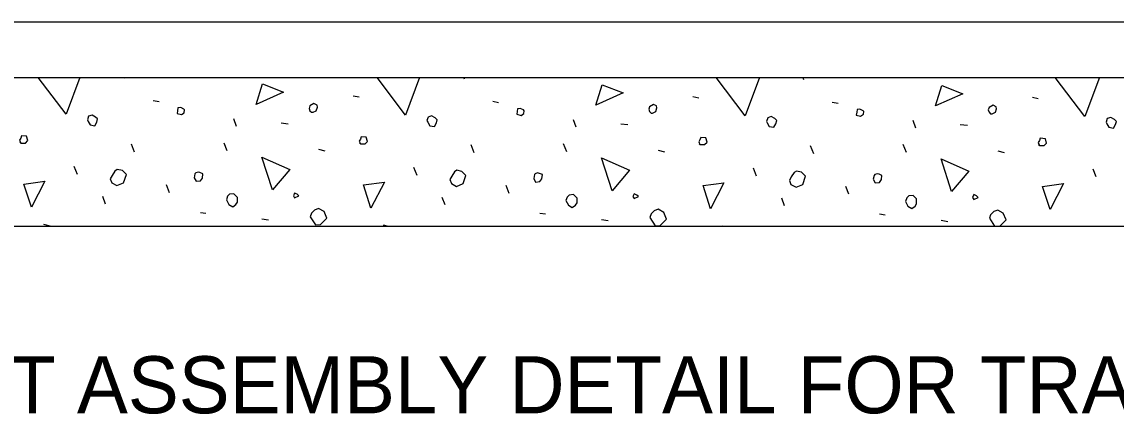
# Model space of a CAD drawing. Extents: x 110698 to 110915, y 110390 to 110472.
# Drawn here: x 110880.112 to 110885.022, y 110456.769 to 110458.529 of the extents above; entities that cross this region are included whole.
import ezdxf

# ---------------------------------------------------------------- set-up
doc = ezdxf.new("R2010")
doc.units = 0
for name, color, linetype in [('Border', 7, 'Continuous'), ('SheetBorder_dp', 7, 'Continuous'), ('SheetLines_dp', 7, 'Continuous'), ('SupstrConc_h', 7, 'Continuous')]:
    doc.layers.add(name, color=color, linetype=linetype)

msp = doc.modelspace()

# ---------------------------------------------------------------- linework, layer by layer
at = {"layer": 'SheetBorder_dp'}
for p, q in [((110880.5736, 110458.2752), (110880.5723, 110458.2787)), ((110882.0974, 110458.2716), (110882.0948, 110458.2787)), ((110883.6212, 110458.2681), (110883.6173, 110458.2787)), ((110881.5989, 110458.1974), (110881.6254, 110458.1921)), ((110883.1227, 110458.1939), (110883.1492, 110458.1885)), ((110884.6465, 110458.1903), (110884.673, 110458.185)), ((110880.7009, 110458.1762), (110880.7274, 110458.1709)), ((110882.2247, 110458.1726), (110882.2512, 110458.1673)), ((110883.7485, 110458.1691), (110883.775, 110458.1638)), ((110881.0756, 110458.0595), (110881.0633, 110458.0931)), ((110882.5995, 110458.056), (110882.5871, 110458.0896)), ((110884.1233, 110458.0524), (110884.1109, 110458.086)), ((110881.2754, 110458.0754), (110881.3072, 110458.0719)), ((110882.7992, 110458.0719), (110882.831, 110458.0683)), ((110884.323, 110458.0683), (110884.3548, 110458.0648)), ((110881.0332, 110457.9499), (110881.0191, 110457.9853)), ((110882.557, 110457.9464), (110882.5429, 110457.9817)), ((110880.6178, 110457.9446), (110880.6036, 110457.98)), ((110881.4433, 110457.957), (110881.4716, 110457.9499)), ((110882.1416, 110457.9411), (110882.1275, 110457.9764)), ((110882.9671, 110457.9534), (110882.9954, 110457.9464)), ((110883.6654, 110457.9375), (110883.6513, 110457.9729)), ((110884.0808, 110457.9428), (110884.0667, 110457.9782)), ((110884.491, 110457.9499), (110884.5192, 110457.9428)), ((110880.3615, 110457.8438), (110880.3473, 110457.8792)), ((110881.8853, 110457.8403), (110881.8711, 110457.8757)), ((110883.4091, 110457.8368), (110883.3949, 110457.8721)), ((110884.9329, 110457.8332), (110884.9188, 110457.8686)), ((110880.7751, 110457.7625), (110880.761, 110457.7979)), ((110882.2989, 110457.759), (110882.2848, 110457.7943)), ((110883.8227, 110457.7554), (110883.8086, 110457.7908)), ((110880.487, 110457.7113), (110880.4746, 110457.7448)), ((110882.0108, 110457.7077), (110881.9984, 110457.7413)), ((110883.5346, 110457.7042), (110883.5222, 110457.7378)), ((110880.913, 110457.6741), (110880.9378, 110457.6706)), ((110881.1888, 110457.6458), (110881.2188, 110457.6405)), ((110882.4368, 110457.6706), (110882.4616, 110457.6671)), ((110882.7126, 110457.6423), (110882.7426, 110457.637)), ((110883.9606, 110457.6671), (110883.9854, 110457.6635)), ((110884.2364, 110457.6388), (110884.2665, 110457.6335)), ((110880.2094, 110457.6211), (110880.2377, 110457.614)), ((110881.7332, 110457.6176), (110881.7553, 110457.612)), ((110883.2571, 110457.614), (110883.265, 110457.612))]:
    msp.add_line(p, q, dxfattribs=at)
for points in [[(110880.3102, 110458.1143), (110880.1852, 110458.2787)], [(110880.3716, 110458.2787), (110880.3102, 110458.1143)], [(110881.834, 110458.1108), (110881.7064, 110458.2787)], [(110881.8968, 110458.2787), (110881.834, 110458.1108)], [(110883.3578, 110458.1072), (110883.2275, 110458.2787)], [(110883.4219, 110458.2787), (110883.3578, 110458.1072)], [(110884.8816, 110458.1037), (110884.7486, 110458.2787)], [(110884.947, 110458.2787), (110884.8816, 110458.1037)], [(110881.164, 110458.1585), (110881.1923, 110458.2504), (110881.286, 110458.2133), (110881.164, 110458.1585)], [(110882.6878, 110458.155), (110882.7161, 110458.2469), (110882.8098, 110458.2098), (110882.6878, 110458.155)], [(110884.2117, 110458.1514), (110884.2399, 110458.2433), (110884.3336, 110458.2062), (110884.2117, 110458.1514)], [(110880.8087, 110458.1178), (110880.8281, 110458.1125), (110880.8405, 110458.1214), (110880.8423, 110458.1337), (110880.8388, 110458.1373), (110880.8246, 110458.1444), (110880.8122, 110458.1426), (110880.8105, 110458.1302), (110880.8087, 110458.1178)], [(110881.4115, 110458.1231), (110881.4186, 110458.1231), (110881.4327, 110458.1302), (110881.438, 110458.1461), (110881.4363, 110458.155), (110881.4221, 110458.162), (110881.4044, 110458.1514), (110881.4009, 110458.1408), (110881.4044, 110458.1302), (110881.4115, 110458.1231)], [(110882.3325, 110458.1143), (110882.352, 110458.109), (110882.3643, 110458.1178), (110882.3661, 110458.1302), (110882.3626, 110458.1337), (110882.3484, 110458.1408), (110882.3361, 110458.1391), (110882.3343, 110458.1267), (110882.3325, 110458.1143)], [(110882.9353, 110458.1196), (110882.9424, 110458.1196), (110882.9565, 110458.1267), (110882.9618, 110458.1426), (110882.9601, 110458.1514), (110882.9459, 110458.1585), (110882.9283, 110458.1479), (110882.9247, 110458.1373), (110882.9283, 110458.1267), (110882.9353, 110458.1196)], [(110883.8563, 110458.1108), (110883.8758, 110458.1055), (110883.8882, 110458.1143), (110883.8899, 110458.1267), (110883.8864, 110458.1302), (110883.8722, 110458.1373), (110883.8599, 110458.1355), (110883.8581, 110458.1231), (110883.8563, 110458.1108)], [(110884.4591, 110458.1161), (110884.4662, 110458.1161), (110884.4804, 110458.1231), (110884.4857, 110458.1391), (110884.4839, 110458.1479), (110884.4697, 110458.155), (110884.4521, 110458.1444), (110884.4485, 110458.1337), (110884.4521, 110458.1231), (110884.4591, 110458.1161)], [(110880.4092, 110458.0825), (110880.418, 110458.0666), (110880.4392, 110458.063), (110880.4481, 110458.0789), (110880.4516, 110458.0931), (110880.4428, 110458.1019), (110880.4269, 110458.1108), (110880.411, 110458.1055), (110880.4057, 110458.0896), (110880.4092, 110458.0825)], [(110881.933, 110458.0789), (110881.9418, 110458.063), (110881.9631, 110458.0595), (110881.9719, 110458.0754), (110881.9754, 110458.0896), (110881.9666, 110458.0984), (110881.9507, 110458.1072), (110881.9348, 110458.1019), (110881.9295, 110458.086), (110881.933, 110458.0789)], [(110883.4568, 110458.0754), (110883.4657, 110458.0595), (110883.4869, 110458.056), (110883.4957, 110458.0719), (110883.4992, 110458.086), (110883.4904, 110458.0949), (110883.4745, 110458.1037), (110883.4586, 110458.0984), (110883.4533, 110458.0825), (110883.4568, 110458.0754)], [(110884.9806, 110458.0719), (110884.9895, 110458.056), (110885.0107, 110458.0524), (110885.0195, 110458.0683), (110885.0231, 110458.0825), (110885.0142, 110458.0913), (110884.9983, 110458.1002), (110884.9824, 110458.0949), (110884.9771, 110458.0789), (110884.9806, 110458.0719)], [(110880.1069, 110457.9853), (110880.1281, 110457.9853), (110880.1387, 110457.9959), (110880.1334, 110458.0153), (110880.1104, 110458.0171), (110880.1069, 110458.0065), (110880.1016, 110457.9976), (110880.1069, 110457.9853), (110880.1034, 110457.9888)], [(110881.6307, 110457.9817), (110881.6519, 110457.9817), (110881.6625, 110457.9923), (110881.6572, 110458.0118), (110881.6343, 110458.0135), (110881.6307, 110458.0029), (110881.6254, 110457.9941), (110881.6307, 110457.9817), (110881.6272, 110457.9853)], [(110883.1545, 110457.9782), (110883.1757, 110457.9782), (110883.1864, 110457.9888), (110883.181, 110458.0082), (110883.1581, 110458.01), (110883.1545, 110457.9994), (110883.1492, 110457.9906), (110883.1545, 110457.9782), (110883.151, 110457.9817)], [(110884.6783, 110457.9746), (110884.6996, 110457.9746), (110884.7102, 110457.9853), (110884.7049, 110458.0047), (110884.6819, 110458.0065), (110884.6783, 110457.9959), (110884.673, 110457.987), (110884.6783, 110457.9746), (110884.6748, 110457.9782)], [(110881.2365, 110457.7749), (110881.1888, 110457.9216), (110881.3143, 110457.8668), (110881.2365, 110457.7749)], [(110882.7603, 110457.7714), (110882.7126, 110457.9181), (110882.8381, 110457.8633), (110882.7603, 110457.7714)], [(110884.2841, 110457.7678), (110884.2364, 110457.9145), (110884.3619, 110457.8597), (110884.2841, 110457.7678)], [(110880.5153, 110457.8067), (110880.5382, 110457.7943), (110880.5683, 110457.8067), (110880.5807, 110457.8438), (110880.563, 110457.8615), (110880.54, 110457.8668), (110880.5294, 110457.8597), (110880.517, 110457.8403), (110880.5082, 110457.8244), (110880.5153, 110457.8067)], [(110880.8847, 110457.8297), (110880.8936, 110457.8138), (110880.913, 110457.8156), (110880.9218, 110457.8279), (110880.9236, 110457.8474), (110880.9112, 110457.8527), (110880.9024, 110457.8544), (110880.8918, 110457.8509), (110880.8883, 110457.8474), (110880.8847, 110457.8297)], [(110882.0391, 110457.8032), (110882.0621, 110457.7908), (110882.0921, 110457.8032), (110882.1045, 110457.8403), (110882.0868, 110457.858), (110882.0638, 110457.8633), (110882.0532, 110457.8562), (110882.0408, 110457.8368), (110882.032, 110457.8209), (110882.0391, 110457.8032)], [(110882.4085, 110457.8262), (110882.4174, 110457.8102), (110882.4368, 110457.812), (110882.4457, 110457.8244), (110882.4474, 110457.8438), (110882.435, 110457.8491), (110882.4262, 110457.8509), (110882.4156, 110457.8474), (110882.4121, 110457.8438), (110882.4085, 110457.8262)], [(110883.5629, 110457.7996), (110883.5859, 110457.7873), (110883.6159, 110457.7996), (110883.6283, 110457.8368), (110883.6106, 110457.8544), (110883.5876, 110457.8597), (110883.577, 110457.8527), (110883.5647, 110457.8332), (110883.5558, 110457.8173), (110883.5629, 110457.7996)], [(110883.9323, 110457.8226), (110883.9412, 110457.8067), (110883.9606, 110457.8085), (110883.9695, 110457.8209), (110883.9712, 110457.8403), (110883.9589, 110457.8456), (110883.95, 110457.8474), (110883.9394, 110457.8438), (110883.9359, 110457.8403), (110883.9323, 110457.8226)], [(110880.1546, 110457.6971), (110880.121, 110457.8014), (110880.2147, 110457.8138), (110880.1546, 110457.6971)], [(110881.6784, 110457.6936), (110881.6449, 110457.7979), (110881.7385, 110457.8102), (110881.6784, 110457.6936)], [(110883.2023, 110457.69), (110883.1687, 110457.7943), (110883.2624, 110457.8067), (110883.2023, 110457.69)], [(110884.7261, 110457.6865), (110884.6925, 110457.7908), (110884.7862, 110457.8032), (110884.7261, 110457.6865)], [(110881.0297, 110457.7307), (110881.0403, 110457.7095), (110881.058, 110457.6989), (110881.0721, 110457.7095), (110881.0792, 110457.7201), (110881.0792, 110457.7413), (110881.0633, 110457.7572), (110881.0438, 110457.7554), (110881.035, 110457.7466), (110881.0297, 110457.7307)], [(110881.3355, 110457.7395), (110881.3549, 110457.7484), (110881.3479, 110457.7554), (110881.3355, 110457.7607), (110881.3302, 110457.7484), (110881.3355, 110457.7395)], [(110882.5535, 110457.7272), (110882.5641, 110457.7059), (110882.5818, 110457.6953), (110882.5959, 110457.7059), (110882.603, 110457.7166), (110882.603, 110457.7378), (110882.5871, 110457.7537), (110882.5676, 110457.7519), (110882.5588, 110457.7431), (110882.5535, 110457.7272)], [(110882.8593, 110457.736), (110882.8788, 110457.7448), (110882.8717, 110457.7519), (110882.8593, 110457.7572), (110882.854, 110457.7448), (110882.8593, 110457.736)], [(110884.0773, 110457.7236), (110884.0879, 110457.7024), (110884.1056, 110457.6918), (110884.1197, 110457.7024), (110884.1268, 110457.713), (110884.1268, 110457.7342), (110884.1109, 110457.7501), (110884.0914, 110457.7484), (110884.0826, 110457.7395), (110884.0773, 110457.7236)], [(110884.3831, 110457.7325), (110884.4026, 110457.7413), (110884.3955, 110457.7484), (110884.3831, 110457.7537), (110884.3778, 110457.7413), (110884.3831, 110457.7325)], [(110881.4062, 110457.6547), (110881.4292, 110457.6176), (110881.4522, 110457.6193), (110881.461, 110457.6282), (110881.4805, 110457.6476), (110881.4681, 110457.6777), (110881.4433, 110457.6918), (110881.4257, 110457.6847), (110881.4115, 110457.6706), (110881.4062, 110457.6547)], [(110882.93, 110457.6511), (110882.953, 110457.614), (110882.976, 110457.6158), (110882.9848, 110457.6246), (110883.0043, 110457.6441), (110882.9919, 110457.6741), (110882.9671, 110457.6883), (110882.9495, 110457.6812), (110882.9353, 110457.6671), (110882.93, 110457.6511)], [(110884.497, 110457.612), (110884.4998, 110457.6123), (110884.5086, 110457.6211), (110884.5281, 110457.6405), (110884.5157, 110457.6706), (110884.491, 110457.6847), (110884.4733, 110457.6777), (110884.4591, 110457.6635), (110884.4538, 110457.6476)], [(110884.4538, 110457.6476), (110884.4759, 110457.612)]]:
    msp.add_lwpolyline(points, dxfattribs=at)
at = {"layer": 'SheetLines_dp'}
for p, q in [((110873.4424, 110458.2787), (110896.2163, 110458.2787)), ((110873.4424, 110457.612), (110896.2163, 110457.612))]:
    msp.add_line(p, q, dxfattribs=at)
at = {"layer": 'SupstrConc_h'}
msp.add_line((110873.4424, 110458.5287), (110896.2163, 110458.5287), dxfattribs=at)

# ---------------------------------------------------------------- texts
at = {"layer": 'Border'}
msp.add_text('PULL POST ASSEMBLY DETAIL FOR TRAFFIC RAILING BARRIERS', height=0.256001, dxfattribs=at).set_placement((110878.3805, 110456.7727))

doc.saveas('drawing.dxf')
